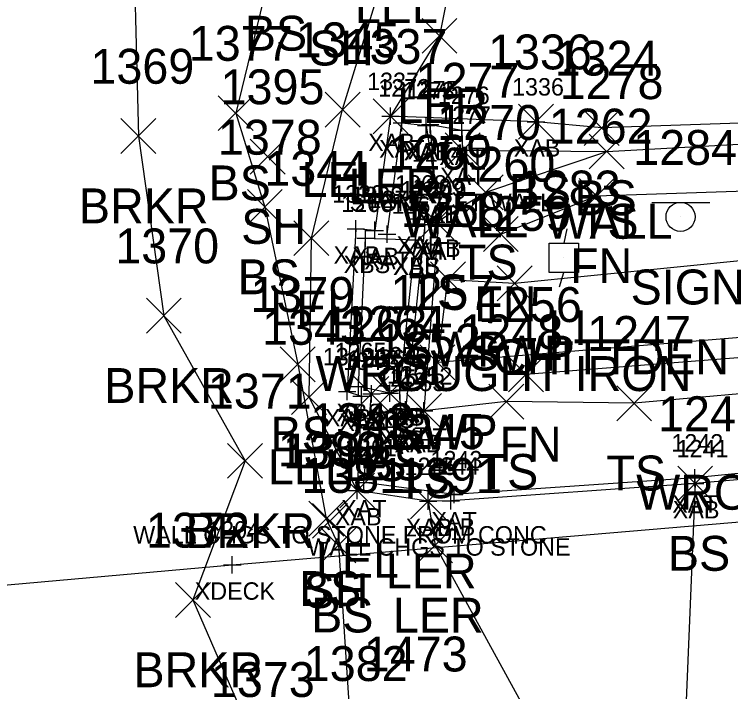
# Model space of a CAD drawing. Extents: x 1505684 to 1510253, y 730355 to 731397.
# Drawn here: x 1510141.47 to 1510182.54, y 730918.48 to 730957.3 of the extents above; entities that cross this region are included whole.
import ezdxf

# ---------------------------------------------------------------- set-up
doc = ezdxf.new("R2010")
doc.units = 0
for name, color, linetype in [('B_A', 7, 'Continuous'), ('B_C', 7, 'Continuous'), ('B_I', 7, 'Continuous'), ('B_TIC', 7, 'Continuous'), ('BELB', 7, 'Continuous'), ('BSE', 7, 'Continuous'), ('BSUBM', 7, 'Continuous'), ('L_A', 7, 'Continuous'), ('L_C', 7, 'Continuous'), ('L_I', 7, 'Continuous'), ('L_TIC', 7, 'Continuous'), ('LARO', 7, 'Continuous'), ('LAWE', 7, 'Continuous'), ('LELB', 7, 'Continuous'), ('LFNC', 7, 'Continuous'), ('LW', 7, 'Continuous'), ('R_A', 7, 'Continuous'), ('R_I', 7, 'Continuous'), ('R_TIC', 7, 'Continuous'), ('RSW', 7, 'Continuous'), ('S_A', 7, 'Continuous'), ('S_C', 7, 'Continuous'), ('S_I', 7, 'Continuous'), ('SSGN', 7, 'Continuous'), ('U_A', 7, 'Continuous'), ('U_I', 7, 'Continuous'), ('ULP', 7, 'Continuous')]:
    doc.layers.add(name, color=color, linetype=linetype)

msp = doc.modelspace()

# ---------------------------------------------------------------- linework, layer by layer
at = {"layer": 'B_TIC'}
for p, q in [((1510163.047, 730951.454), (1510163.123, 730951.454)), ((1510171.383, 730951.139), (1510171.459, 730951.139)), ((1510163.686, 730951.085), (1510163.762, 730951.085)), ((1510165.09, 730950.922), (1510165.166, 730950.922)), ((1510165.09, 730950.922), (1510165.166, 730950.922)), ((1510165.316, 730950.98), (1510165.391, 730950.98)), ((1510165.316, 730950.98), (1510165.391, 730950.98)), ((1510167.129, 730950.654), (1510167.205, 730950.654)), ((1510167.175, 730949.513), (1510167.251, 730949.513)), ((1510165.615, 730947.345), (1510165.691, 730947.345)), ((1510165.615, 730947.345), (1510165.691, 730947.345)), ((1510164.667, 730945.574), (1510164.743, 730945.574)), ((1510165.665, 730945.391), (1510165.74, 730945.391)), ((1510161.054, 730945.001), (1510161.13, 730945.001)), ((1510165.012, 730945.243), (1510165.087, 730945.243)), ((1510165.774, 730945.224), (1510165.849, 730945.224)), ((1510165.774, 730945.224), (1510165.849, 730945.224)), ((1510162.141, 730944.915), (1510162.216, 730944.915)), ((1510162.844, 730944.69), (1510162.919, 730944.69)), ((1510161.614, 730944.464), (1510161.69, 730944.464)), ((1510164.47, 730944.365), (1510164.546, 730944.365)), ((1510164.47, 730944.365), (1510164.546, 730944.365)), ((1510161.207, 730935.973), (1510161.283, 730935.973)), ((1510160.556, 730935.677), (1510160.631, 730935.677)), ((1510161.948, 730935.542), (1510162.023, 730935.542)), ((1510163.002, 730935.582), (1510163.078, 730935.582)), ((1510163.576, 730935.73), (1510163.652, 730935.73)), ((1510163.576, 730935.73), (1510163.652, 730935.73)), ((1510161.389, 730935.415), (1510161.464, 730935.415)), ((1510163.631, 730934.447), (1510163.706, 730934.447)), ((1510163.903, 730934.634), (1510163.979, 730934.634)), ((1510164.96, 730934.568), (1510165.036, 730934.568)), ((1510164.96, 730934.568), (1510165.036, 730934.568)), ((1510164.555, 730934.2), (1510164.63, 730934.2)), ((1510180.488, 730930.735), (1510180.563, 730930.735)), ((1510161.512, 730930.465), (1510161.587, 730930.465)), ((1510180.505, 730930.404), (1510180.581, 730930.404)), ((1510161.132, 730930.005), (1510161.207, 730930.005)), ((1510161.132, 730930.005), (1510161.207, 730930.005)), ((1510166.683, 730929.771), (1510166.759, 730929.771)), ((1510165.197, 730929.39), (1510165.273, 730929.39)), ((1510166.502, 730929.412), (1510166.577, 730929.412)), ((1510153.975, 730925.744), (1510154.05, 730925.744))]:
    msp.add_line(p, q, dxfattribs=at)
for points in [[(1510163.044, 730950.954), (1510163.044, 730951.954)], [(1510163.683, 730950.585), (1510163.683, 730951.585)], [(1510171.38, 730950.639), (1510171.38, 730951.639)], [(1510162.544, 730951.454), (1510163.544, 730951.454)], [(1510165.087, 730950.422), (1510165.087, 730951.422)], [(1510165.087, 730950.422), (1510165.087, 730951.422)], [(1510165.312, 730950.48), (1510165.312, 730951.48)], [(1510165.312, 730950.48), (1510165.312, 730951.48)], [(1510167.126, 730950.154), (1510167.126, 730951.154)], [(1510170.88, 730951.139), (1510171.88, 730951.139)], [(1510163.183, 730951.085), (1510164.183, 730951.085)], [(1510164.587, 730950.922), (1510165.587, 730950.922)], [(1510164.587, 730950.922), (1510165.587, 730950.922)], [(1510164.812, 730950.98), (1510165.812, 730950.98)], [(1510164.812, 730950.98), (1510165.812, 730950.98)], [(1510166.626, 730950.654), (1510167.626, 730950.654)], [(1510167.172, 730949.013), (1510167.172, 730950.013)], [(1510166.672, 730949.513), (1510167.672, 730949.513)], [(1510165.612, 730946.845), (1510165.612, 730947.845)], [(1510165.612, 730946.845), (1510165.612, 730947.845)], [(1510165.112, 730947.345), (1510166.112, 730947.345)], [(1510165.112, 730947.345), (1510166.112, 730947.345)], [(1510164.664, 730945.074), (1510164.664, 730946.074)], [(1510165.661, 730944.891), (1510165.661, 730945.891)], [(1510161.051, 730944.501), (1510161.051, 730945.501)], [(1510162.137, 730944.415), (1510162.137, 730945.415)], [(1510164.164, 730945.574), (1510165.164, 730945.574)], [(1510165.008, 730944.743), (1510165.008, 730945.743)], [(1510165.161, 730945.391), (1510166.161, 730945.391)], [(1510165.77, 730944.724), (1510165.77, 730945.724)], [(1510165.77, 730944.724), (1510165.77, 730945.724)], [(1510160.551, 730945.001), (1510161.551, 730945.001)], [(1510161.611, 730943.964), (1510161.611, 730944.964)], [(1510162.84, 730944.19), (1510162.84, 730945.19)], [(1510164.508, 730945.243), (1510165.508, 730945.243)], [(1510165.27, 730945.224), (1510166.27, 730945.224)], [(1510165.27, 730945.224), (1510166.27, 730945.224)], [(1510161.637, 730944.915), (1510162.637, 730944.915)], [(1510162.34, 730944.69), (1510163.34, 730944.69)], [(1510164.467, 730943.865), (1510164.467, 730944.865)], [(1510164.467, 730943.865), (1510164.467, 730944.865)], [(1510161.111, 730944.464), (1510162.111, 730944.464)], [(1510163.967, 730944.365), (1510164.967, 730944.365)], [(1510163.967, 730944.365), (1510164.967, 730944.365)], [(1510161.204, 730935.473), (1510161.204, 730936.473)], [(1510160.553, 730935.177), (1510160.553, 730936.177)], [(1510160.704, 730935.973), (1510161.704, 730935.973)], [(1510161.944, 730935.042), (1510161.944, 730936.042)], [(1510162.999, 730935.082), (1510162.999, 730936.082)], [(1510163.573, 730935.23), (1510163.573, 730936.23)], [(1510163.573, 730935.23), (1510163.573, 730936.23)], [(1510160.053, 730935.677), (1510161.053, 730935.677)], [(1510161.386, 730934.915), (1510161.386, 730935.915)], [(1510161.444, 730935.542), (1510162.444, 730935.542)], [(1510162.499, 730935.582), (1510163.499, 730935.582)], [(1510163.073, 730935.73), (1510164.073, 730935.73)], [(1510163.073, 730935.73), (1510164.073, 730935.73)], [(1510160.886, 730935.415), (1510161.886, 730935.415)], [(1510163.9, 730934.134), (1510163.9, 730935.134)], [(1510163.627, 730933.947), (1510163.627, 730934.947)], [(1510164.551, 730933.7), (1510164.551, 730934.7)], [(1510164.957, 730934.068), (1510164.957, 730935.068)], [(1510164.957, 730934.068), (1510164.957, 730935.068)], [(1510163.127, 730934.447), (1510164.127, 730934.447)], [(1510163.4, 730934.634), (1510164.4, 730934.634)], [(1510164.457, 730934.568), (1510165.457, 730934.568)], [(1510164.457, 730934.568), (1510165.457, 730934.568)], [(1510164.051, 730934.2), (1510165.051, 730934.2)], [(1510180.484, 730930.235), (1510180.484, 730931.235)], [(1510161.508, 730929.965), (1510161.508, 730930.965)], [(1510179.984, 730930.735), (1510180.984, 730930.735)], [(1510180.502, 730929.904), (1510180.502, 730930.904)], [(1510161.008, 730930.465), (1510162.008, 730930.465)], [(1510161.128, 730929.505), (1510161.128, 730930.505)], [(1510161.128, 730929.505), (1510161.128, 730930.505)], [(1510166.68, 730929.271), (1510166.68, 730930.271)], [(1510180.002, 730930.404), (1510181.002, 730930.404)], [(1510160.628, 730930.005), (1510161.628, 730930.005)], [(1510160.628, 730930.005), (1510161.628, 730930.005)], [(1510165.194, 730928.89), (1510165.194, 730929.89)], [(1510166.18, 730929.771), (1510167.18, 730929.771)], [(1510166.498, 730928.912), (1510166.498, 730929.912)], [(1510164.694, 730929.39), (1510165.694, 730929.39)], [(1510165.998, 730929.412), (1510166.998, 730929.412)], [(1510153.971, 730925.244), (1510153.971, 730926.244)], [(1510153.471, 730925.744), (1510154.471, 730925.744)]]:
    msp.add_lwpolyline(points, dxfattribs=at)
at = {"layer": 'BELB'}
msp.add_lwpolyline([(1510096.423, 730920.568), (1510096.258, 730921.164), (1510097.476, 730920.718), (1510153.971, 730925.744), (1510189.37, 730928.753), (1510189.909, 730929.156), (1510190.209, 730929.584)], dxfattribs=at)
at = {"layer": 'BSE'}
msp.add_lwpolyline([(1510163.573, 730935.73), (1510162.999, 730935.582), (1510161.204, 730935.973), (1510161.611, 730944.464), (1510164.467, 730944.365)], dxfattribs=at)
at = {"layer": 'BSUBM'}
for points in [[(1510171.38, 730951.139), (1510163.044, 730951.454), (1510162.137, 730944.915), (1510161.051, 730945.001), (1510160.553, 730935.677), (1510161.386, 730935.415), (1510161.128, 730930.005)], [(1510162.84, 730944.69), (1510163.683, 730951.085), (1510165.087, 730950.922), (1510165.312, 730950.98), (1510167.126, 730950.654), (1510167.172, 730949.513)], [(1510165.087, 730950.922), (1510165.612, 730947.345)], [(1510165.612, 730947.345), (1510165.312, 730950.98)], [(1510164.551, 730934.2), (1510163.627, 730934.447), (1510163.573, 730935.73), (1510164.467, 730944.365), (1510164.664, 730945.574), (1510165.661, 730945.391)], [(1510165.77, 730945.224), (1510165.008, 730945.243), (1510163.9, 730934.634), (1510164.957, 730934.568)], [(1510165.77, 730945.224), (1510164.957, 730934.568)], [(1510188.755, 730931.387), (1510187.35, 730931.428), (1510180.484, 730930.735), (1510166.68, 730929.771), (1510161.508, 730930.465), (1510161.944, 730935.542)], [(1510191.193, 730933.234), (1510188.755, 730931.387), (1510188.784, 730931.125), (1510187.731, 730931.05), (1510187.305, 730930.998), (1510180.502, 730930.404), (1510166.498, 730929.412), (1510165.194, 730929.39), (1510161.128, 730930.005)]]:
    msp.add_lwpolyline(points, dxfattribs=at)
at = {"layer": 'L_TIC'}
for points in [[(1510164.845, 730955.06), (1510166.845, 730957.06)], [(1510166.845, 730955.06), (1510164.845, 730957.06)], [(1510159.297, 730950.834), (1510161.297, 730952.834)], [(1510161.297, 730950.834), (1510159.297, 730952.834)], [(1510153.169, 730950.632), (1510155.169, 730952.632)], [(1510155.169, 730950.632), (1510153.169, 730952.632)], [(1510162.044, 730950.454), (1510164.044, 730952.454)], [(1510164.044, 730950.454), (1510162.044, 730952.454)], [(1510170.38, 730950.139), (1510172.38, 730952.139)], [(1510172.38, 730950.139), (1510170.38, 730952.139)], [(1510174.146, 730949.785), (1510176.146, 730951.785)], [(1510176.146, 730949.785), (1510174.146, 730951.785)], [(1510147.587, 730949.317), (1510149.587, 730951.317)], [(1510149.587, 730949.317), (1510147.587, 730951.317)], [(1510166.172, 730948.513), (1510168.172, 730950.513)], [(1510168.172, 730948.513), (1510166.172, 730950.513)], [(1510174.432, 730948.435), (1510176.432, 730950.435)], [(1510176.432, 730948.435), (1510174.432, 730950.435)], [(1510174.432, 730948.435), (1510176.432, 730950.435)], [(1510176.432, 730948.435), (1510174.432, 730950.435)], [(1510154.993, 730948.141), (1510156.993, 730950.141)], [(1510156.993, 730948.141), (1510154.993, 730950.141)], [(1510167.497, 730946.097), (1510169.497, 730948.097)], [(1510169.497, 730946.097), (1510167.497, 730948.097)], [(1510173.852, 730945.889), (1510175.852, 730947.889)], [(1510175.852, 730945.889), (1510173.852, 730947.889)], [(1510154.837, 730945.251), (1510156.837, 730947.251)], [(1510156.837, 730945.251), (1510154.837, 730947.251)], [(1510164.661, 730944.391), (1510166.661, 730946.391)], [(1510166.661, 730944.391), (1510164.661, 730946.391)], [(1510157.502, 730943.467), (1510159.502, 730945.467)], [(1510159.502, 730943.467), (1510157.502, 730945.467)], [(1510168.364, 730943.705), (1510170.364, 730945.705)], [(1510170.364, 730943.705), (1510168.364, 730945.705)], [(1510149.043, 730939.021), (1510151.043, 730941.021)], [(1510151.043, 730939.021), (1510149.043, 730941.021)], [(1510156.72, 730936.242), (1510158.72, 730938.242)], [(1510158.72, 730936.242), (1510156.72, 730938.242)], [(1510169.804, 730935.66), (1510171.804, 730937.66)], [(1510171.804, 730935.66), (1510169.804, 730937.66)], [(1510157.373, 730934.357), (1510159.373, 730936.357)], [(1510159.373, 730934.357), (1510157.373, 730936.357)], [(1510160.944, 730934.542), (1510162.944, 730936.542)], [(1510162.944, 730934.542), (1510160.944, 730936.542)], [(1510161.999, 730934.582), (1510163.999, 730936.582)], [(1510163.999, 730934.582), (1510161.999, 730936.582)], [(1510168.681, 730934.098), (1510170.681, 730936.098)], [(1510170.681, 730934.098), (1510168.681, 730936.098)], [(1510176.007, 730934.007), (1510178.007, 730936.007)], [(1510178.007, 730934.007), (1510176.007, 730936.007)], [(1510163.957, 730933.568), (1510165.957, 730935.568)], [(1510165.957, 730933.568), (1510163.957, 730935.568)], [(1510153.699, 730930.705), (1510155.699, 730932.705)], [(1510155.699, 730930.705), (1510153.699, 730932.705)], [(1510160.128, 730929.005), (1510162.128, 730931.005)], [(1510162.128, 730929.005), (1510160.128, 730931.005)], [(1510179.502, 730929.404), (1510181.502, 730931.404)], [(1510181.502, 730929.404), (1510179.502, 730931.404)], [(1510164.194, 730928.39), (1510166.194, 730930.39)], [(1510166.194, 730928.39), (1510164.194, 730930.39)], [(1510158.355, 730927.387), (1510160.355, 730929.387)], [(1510160.355, 730927.387), (1510158.355, 730929.387)], [(1510158.57, 730927.267), (1510160.57, 730929.267)], [(1510160.57, 730927.267), (1510158.57, 730929.267)], [(1510159.052, 730925.869), (1510161.052, 730927.869)], [(1510161.052, 730925.869), (1510159.052, 730927.869)], [(1510164.596, 730925.859), (1510166.596, 730927.859)], [(1510166.596, 730925.859), (1510164.596, 730927.859)], [(1510150.716, 730922.73), (1510152.716, 730924.73)], [(1510152.716, 730922.73), (1510150.716, 730924.73)]]:
    msp.add_lwpolyline(points, dxfattribs=at)
at = {"layer": 'LARO'}
for points in [[(1510161.128, 730930.005), (1510158.373, 730935.357), (1510158.502, 730944.467), (1510160.297, 730951.834), (1510163.353, 730961.789), (1510164.438, 730969.672), (1510168.214, 730979.63), (1510167.547, 730987.697), (1510165.484, 730988.873)], [(1510173.671, 730983.007), (1510173.163, 730979.018), (1510170.338, 730969.187), (1510170.201, 730962.539), (1510167.147, 730962.543), (1510165.845, 730956.06), (1510163.044, 730951.454)], [(1510165.194, 730929.39), (1510165.596, 730926.859), (1510177.92, 730904.378), (1510177.778, 730901.597), (1510173.423, 730893.43), (1510175.272, 730880.225)]]:
    msp.add_lwpolyline(points, dxfattribs=at)
at = {"layer": 'LAWE'}
msp.add_lwpolyline([(1510147.562, 730990.156), (1510149.891, 730976.157), (1510148.239, 730964.543), (1510148.587, 730950.317), (1510150.043, 730940.021), (1510154.699, 730931.705), (1510151.716, 730923.73), (1510155.439, 730915.171), (1510157.525, 730908.642), (1510159.748, 730889.351), (1510165.212, 730879.843)], dxfattribs=at)
at = {"layer": 'LELB'}
for points in [[(1510211.127, 730983.825), (1510214.547, 730974.081), (1510212.454, 730970.755), (1510214.424, 730965.024), (1510219.359, 730956.811), (1510217.995, 730956.45), (1510207.598, 730962.932), (1510199.546, 730964.713), (1510193.439, 730958.459), (1510194.352, 730951.448), (1510175.146, 730950.785), (1510171.38, 730951.139)], [(1510151.004, 730976.626), (1510156.58, 730971.051), (1510156.251, 730960.212), (1510154.169, 730951.632), (1510155.837, 730946.251), (1510157.72, 730937.242), (1510159.355, 730928.387), (1510160.052, 730926.869), (1510160.762, 730916.086), (1510163.632, 730906.312), (1510169.271, 730896.105), (1510172.686, 730876.272)], [(1510165.661, 730945.391), (1510168.497, 730947.097), (1510175.432, 730949.435)], [(1510161.944, 730935.542), (1510162.999, 730935.582)], [(1510191.959, 730933.968), (1510189.421, 730935.915), (1510186.959, 730935.882), (1510177.007, 730935.007), (1510169.681, 730935.098), (1510164.957, 730934.568)], [(1510180.502, 730930.404), (1510179.372, 730903.209), (1510178.676, 730894.605), (1510182.197, 730888.37)]]:
    msp.add_lwpolyline(points, dxfattribs=at)
at = {"layer": 'LFNC'}
for points in [[(1510169.364, 730944.705), (1510174.852, 730946.889), (1510198.879, 730947.692)], [(1510186.849, 730937.905), (1510170.804, 730936.66)]]:
    msp.add_lwpolyline(points, dxfattribs=at)
at = {"layer": 'LW'}
msp.add_lwpolyline([(1510167.172, 730949.513), (1510175.432, 730949.435), (1510197.45, 730950.656)], dxfattribs=at)
at = {"layer": 'R_TIC'}
for points in [[(1510165.329, 730941.107), (1510167.329, 730943.107)], [(1510167.329, 730941.107), (1510165.329, 730943.107)], [(1510169.157, 730940.882), (1510171.157, 730942.882)], [(1510171.157, 730940.882), (1510169.157, 730942.882)], [(1510164.729, 730936.348), (1510166.729, 730938.348)], [(1510166.729, 730936.348), (1510164.729, 730938.348)]]:
    msp.add_lwpolyline(points, dxfattribs=at)
at = {"layer": 'RSW'}
msp.add_lwpolyline([(1510240.267, 730935.792), (1510231.735, 730937.908), (1510223.067, 730940.277), (1510212.685, 730943.587), (1510187.037, 730939.098), (1510165.729, 730937.348), (1510166.329, 730942.107), (1510170.157, 730941.882), (1510188.417, 730943.719), (1510202.952, 730946.804), (1510212.746, 730947.623), (1510229.176, 730943.355), (1510241.241, 730940.486)], dxfattribs=at)
at = {"layer": 'SSGN'}
for p, q in [((1510178.02, 730946.52), (1510181.353, 730946.52)), ((1510179.667, 730945.687), (1510179.667, 730945.687))]:
    msp.add_line(p, q, dxfattribs=at)
msp.add_circle((1510179.667, 730945.687), 0.833, dxfattribs=at)
at = {"layer": 'ULP'}
for p, q in [((1510173.141, 730945.006), (1510172.974, 730944.173)), ((1510172.141, 730942.506), (1510172.141, 730944.173)), ((1510172.141, 730944.173), (1510173.808, 730944.173)), ((1510173.808, 730944.173), (1510173.808, 730942.506)), ((1510172.974, 730943.339), (1510172.974, 730943.339)), ((1510173.808, 730942.506), (1510172.141, 730942.506)), ((1510172.724, 730941.673), (1510172.974, 730942.506))]:
    msp.add_line(p, q, dxfattribs=at)

# ---------------------------------------------------------------- texts
at = {"layer": 'B_A'}
for s, p in [('XAB', (1510161.764, 730949.454)), ('XAT', (1510162.388, 730949.085)), ('XAT', (1510163.792, 730948.922)), ('XAB', (1510163.807, 730948.922)), ('XAT', (1510164.017, 730948.98)), ('XAT', (1510164.017, 730948.98)), ('XAB', (1510170.1, 730949.139)), ('XAT', (1510165.831, 730948.654)), ('XAT', (1510165.877, 730947.513)), ('XAT', (1510164.317, 730945.345)), ('XAB', (1510164.332, 730945.345)), ('XAB', (1510163.384, 730943.574)), ('XAT', (1510163.713, 730943.243)), ('XAB', (1510164.382, 730943.391)), ('XAT', (1510164.475, 730943.224)), ('XAT', (1510164.475, 730943.224)), ('XAB', (1510159.771, 730943.001)), ('XAB', (1510160.858, 730942.915)), ('XBS', (1510160.351, 730942.464)), ('XAT', (1510161.545, 730942.69)), ('XAB', (1510163.187, 730942.365)), ('XBS', (1510163.207, 730942.365)), ('XBS', (1510159.944, 730933.973)), ('XAB', (1510162.293, 730933.73)), ('XBS', (1510162.313, 730933.73)), ('XAB', (1510159.273, 730933.677)), ('XAB', (1510160.106, 730933.415)), ('XAT', (1510160.649, 730933.542)), ('XBS', (1510161.739, 730933.582)), ('XAT', (1510162.604, 730932.634)), ('XAT', (1510163.662, 730932.568)), ('XAT', (1510163.662, 730932.568)), ('XAB', (1510162.348, 730932.447)), ('XAB', (1510163.272, 730932.2)), ('XAT', (1510160.213, 730928.465)), ('XAT', (1510179.189, 730928.735)), ('XAB', (1510179.222, 730928.404)), ('XAB', (1510159.849, 730928.005)), ('XAB', (1510159.849, 730928.005)), ('XAT', (1510165.384, 730927.771)), ('XAB', (1510163.914, 730927.39)), ('XAB', (1510165.219, 730927.412)), ('XDECK', (1510151.814, 730923.744))]:
    msp.add_text(s, height=1, dxfattribs=at).set_placement(p)
at = {"layer": 'B_C'}
for s, p in [('STONE RET WALL', (1510160.699, 730946.013)), ('WALL CHGS TO STONE FROM CONC', (1510148.292, 730926.965)), ('WALL CHGS TO STONE', (1510158.278, 730926.271))]:
    msp.add_text(s, height=1, dxfattribs=at).set_placement(p)
at = {"layer": 'B_I'}
for s, p in [('1337', (1510161.697, 730952.954)), ('1272', (1510162.337, 730952.585)), ('1336', (1510170.006, 730952.639)), ('1273', (1510163.741, 730952.422)), ('1273', (1510163.741, 730952.422)), ('1275', (1510163.966, 730952.48)), ('1275', (1510163.966, 730952.48)), ('1276', (1510165.752, 730952.154)), ('1277', (1510165.825, 730951.013)), ('1274', (1510164.265, 730948.845)), ('1274', (1510164.265, 730948.845)), ('1268', (1510163.293, 730947.074)), ('1269', (1510164.287, 730946.891)), ('1339', (1510159.7, 730946.501)), ('1338', (1510160.791, 730946.415)), ('1250', (1510163.618, 730946.743)), ('1249', (1510164.42, 730946.724)), ('1249', (1510164.42, 730946.724)), ('1271', (1510161.777, 730946.19)), ('1266', (1510160.213, 730945.964)), ('1267', (1510163.096, 730945.865)), ('1267', (1510163.096, 730945.865)), ('1265', (1510159.834, 730937.473)), ('1340', (1510159.163, 730937.177)), ('1263', (1510160.574, 730937.042)), ('1264', (1510161.629, 730937.082)), ('1255', (1510162.226, 730937.23)), ('1255', (1510162.226, 730937.23)), ('1341', (1510160.323, 730936.915)), ('1254', (1510162.281, 730935.947)), ('1251', (1510162.837, 730936.134)), ('1252', (1510163.611, 730936.068)), ('1252', (1510163.611, 730936.068)), ('1253', (1510163.205, 730935.7)), ('1242', (1510179.138, 730932.235)), ('1261', (1510160.422, 730931.965)), ('1241', (1510179.439, 730931.904)), ('1342', (1510159.782, 730931.505)), ('1342', (1510159.782, 730931.505)), ('1243', (1510165.333, 730931.271)), ('1245', (1510163.847, 730930.89)), ('1244', (1510165.152, 730930.912)), ('1204', (1510152.585, 730927.244))]:
    msp.add_text(s, height=1, dxfattribs=at).set_placement(p)
at = {"layer": 'L_A'}
for s, p in [('LEL', (1510160.991, 730956.789)), ('BS', (1510154.692, 730955.212)), ('SH', (1510158.369, 730954.364)), ('LER', (1510163.428, 730951.06)), ('BS', (1510152.61, 730946.632)), ('LEL', (1510157.935, 730946.834)), ('LER', (1510160.626, 730946.454)), ('BS', (1510169.821, 730946.139)), ('BS', (1510173.587, 730945.785)), ('BRKR', (1510145.177, 730945.317)), ('WALL', (1510163.66, 730944.513)), ('WALL', (1510171.92, 730944.435)), ('TS', (1510173.842, 730944.435)), ('SH', (1510154.481, 730944.141)), ('TS', (1510166.907, 730942.097)), ('FN', (1510173.332, 730941.889)), ('BS', (1510154.278, 730941.251)), ('TS', (1510164.071, 730940.391)), ('FN', (1510167.844, 730939.705)), ('LEL', (1510156.139, 730939.467)), ('BRKR', (1510146.633, 730935.021)), ('BS', (1510156.161, 730932.242)), ('FN', (1510169.284, 730931.66)), ('LEL', (1510156.011, 730930.357)), ('BS', (1510160.385, 730930.542)), ('BS', (1510161.44, 730930.582)), ('TS', (1510168.091, 730930.098)), ('TS', (1510175.416, 730930.007)), ('TS', (1510163.366, 730929.568)), ('BRKR', (1510151.289, 730926.705)), ('BS', (1510178.943, 730925.404)), ('LEL', (1510158.766, 730925.005)), ('LER', (1510162.777, 730924.39)), ('BS', (1510157.796, 730923.387)), ('SH', (1510158.058, 730923.267)), ('BS', (1510158.493, 730921.869)), ('LER', (1510163.179, 730921.859)), ('BRKR', (1510148.306, 730918.73))]:
    msp.add_text(s, height=2, dxfattribs=at).set_placement(p)
at = {"layer": 'L_C'}
for s, p in [('WROUGHT IRON', (1510158.742, 730935.705)), ('WROUGT IRON', (1510177.125, 730928.905))]:
    msp.add_text(s, height=2, dxfattribs=at).set_placement(p)
at = {"layer": 'L_I'}
for s, p in [('1377', (1510151.476, 730954.632)), ('1345', (1510157.604, 730954.834)), ('1337', (1510160.351, 730954.454)), ('1336', (1510168.632, 730954.139)), ('1324', (1510172.453, 730953.785)), ('1369', (1510145.839, 730953.317)), ('1277', (1510164.479, 730952.513)), ('1278', (1510172.739, 730952.435)), ('1278', (1510172.739, 730952.435)), ('1395', (1510153.3, 730952.141)), ('1270', (1510165.718, 730950.097)), ('1262', (1510172.112, 730949.889)), ('1378', (1510153.144, 730949.251)), ('1269', (1510162.913, 730948.391)), ('1344', (1510155.809, 730947.467)), ('1260', (1510166.537, 730947.705)), ('1370', (1510147.263, 730943.021)), ('1379', (1510155.019, 730940.242)), ('1256', (1510168.056, 730939.66)), ('1263', (1510159.204, 730938.542)), ('1264', (1510160.259, 730938.582)), ('1343', (1510155.681, 730938.357)), ('1248', (1510166.989, 730938.098)), ('1247', (1510174.314, 730938.007)), ('1252', (1510162.264, 730937.568)), ('1371', (1510152.573, 730934.705)), ('1241', (1510178.376, 730933.404)), ('1342', (1510158.435, 730933.005)), ('1245', (1510162.501, 730932.39)), ('1380', (1510156.576, 730931.387)), ('1392', (1510156.877, 730931.267)), ('1381', (1510157.926, 730929.869)), ('1391', (1510163.47, 730929.859)), ('1372', (1510149.023, 730926.73)), ('1473', (1510161.51, 730919.634)), ('1382', (1510158.069, 730919.086)), ('1373', (1510152.746, 730918.171))]:
    msp.add_text(s, height=2, dxfattribs=at).set_placement(p)
at = {"layer": 'R_A'}
for p in [(1510163.692, 730937.107), (1510167.519, 730936.882), (1510163.091, 730932.348)]:
    msp.add_text('SWP', height=2, dxfattribs=at).set_placement(p)
at = {"layer": 'R_I'}
for s, p in [('1258', (1510163.636, 730945.107)), ('1259', (1510167.456, 730944.882)), ('1257', (1510163.036, 730940.348))]:
    msp.add_text(s, height=2, dxfattribs=at).set_placement(p)
at = {"layer": 'S_A'}
msp.add_text('SIGN', height=2, dxfattribs=at).set_placement((1510176.805, 730940.667))
at = {"layer": 'S_C'}
msp.add_text('CHITTDEN MILL', height=2, dxfattribs=at).set_placement((1510168.923, 730936.667))
at = {"layer": 'S_I'}
msp.add_text('1284', height=2, dxfattribs=at).set_placement((1510176.954, 730948.667))
at = {"layer": 'U_A'}
msp.add_text('LI', height=2, dxfattribs=at).set_placement((1510172.077, 730938.339))
at = {"layer": 'U_I'}
msp.add_text('1283', height=2, dxfattribs=at).set_placement((1510170.281, 730946.339))

doc.saveas('drawing.dxf')
